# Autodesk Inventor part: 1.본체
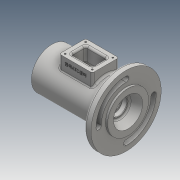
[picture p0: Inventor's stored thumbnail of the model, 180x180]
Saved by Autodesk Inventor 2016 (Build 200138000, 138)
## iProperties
Created: 2017-05
Part Number: 1.본체
Material: Generic
Document SubType Name: Modeling
Designer: Administrator
Density: 1 g/cm^3
Appearance: Default
Author: Administrator
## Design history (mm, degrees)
sketch "스케치1"
  geometry: L1 (-56, 31)-(59, 31); L2 (59, 31)-(59, 0); L3 (59, 0)-(-56, 0); L4 (-56, 0)-(-56, 31); L5 (56, 0)-(46, 0); L6 (46, 0)-(46, 53); L7 (46, 53)-(56, 53); L8 (56, 53)-(56, 0); 1 further point
  constraints: 16 end point, 4 parallel, 2 horizontal, 2 perpendicular, 2 point on line
  dimensions: "d0" = 115 distance of L1.start L1.end; "d1" = 62 diameter of L1 L3; "d2" = 13 distance between parallel lines of L2 L6; "d3" = 3 distance between parallel lines of L2 L8; "d4" = 106 diameter of L7 L3; "d5" = 56 distance from line of point (0, 0) L4
revolve "회전1" sketch "스케치1" stored, may be unused: angle "d6" = 90 deg
node "작업 평면1"
sketch "스케치2"
  geometry: L1 (-25, -20)-(25, -20); L2 (25, -20)-(25, 20); L3 (25, 20)-(-25, 20); L4 (-25, 20)-(-25, -20); L5 (-25, -20)-(25, 20); L6 (25, -20)-(-25, 20); 1 further point
  constraints: 12 end point, 2 midpoint, 2 parallel, 1 horizontal, 1 perpendicular
  dimensions: "d8" = 50 distance of L2.end L3.end; "d9" = 40 distance of L3.end L1.start
extrude "돌출1" join sketch "스케치2" stored distance "d10" = 10; taper "d11" = 0 deg
sketch "스케치3"
  geometry: L1 (-56, -31)-(-59, -31) reference; L2 (-59, -31)-(-59, 31) reference; L3 (-59, 31)-(-56, 31) reference; L4 (-56, 31)-(-56, 53) reference; L5 (-56, 53)-(-46, 53) reference; L6 (-46, 53)-(-46, 31) reference; L7 (-46, 31)-(-25, 31) reference; L8 (-25, 31)-(-25, 44) reference; L9 (-25, 44)-(25, 44) reference; L10 (25, 44)-(25, 31) reference; L11 (25, 31)-(56, 31) reference; L12 (56, 31)-(56, -31) reference; L13 (56, -31)-(-46, -31) reference; L14 (-46, -31)-(-46, -53) reference; L15 (-46, -53)-(-56, -53) reference; L16 (-56, -53)-(-56, -31) reference; L17 (56, 0)-(-59, 0); L18 (56, 0)-(47, 0); L19 (47, 0)-(47, 21); L20 (47, 21)-(56, 21); L21 (56, 21)-(56, 0); L22 (47, 0)-(44, 0); L23 (44, 0)-(44, 24); L24 (44, 24)-(47, 24); L25 (47, 24)-(47, 0); L26 (44, 0)-(35, 0); L27 (35, 0)-(35, 20); L28 (35, 20)-(44, 20); L29 (44, 20)-(44, 0); L30 (35, 0)-(31.75, 0); L31 (31.75, 0)-(31.75, 17.5); L32 (31.75, 17.5)-(35, 17.5); L33 (35, 17.5)-(35, 0); L34 (31.75, 0)-(30, 0); L35 (30, 0)-(30, 18.5); L36 (30, 18.5)-(31.75, 18.5); L37 (31.75, 18.5)-(31.75, 0); L38 (30, 0)-(19, 0); L39 (19, 0)-(19, 17.5); L40 (19, 17.5)-(30, 17.5); L41 (30, 17.5)-(30, 0); L42 (19, 0)-(-19, 0); L43 (-19, 0)-(-19, 23); L44 (-16, 26)-(16, 26); L45 (19, 23)-(19, 0); L46 (-19, 0)-(-30, 0); L47 (-30, 0)-(-30, 17.2); L48 (-29.7, 17.5)-(-19, 17.5); L49 (-19, 17.5)-(-19, 0); L50 (-30, 0)-(-35, 0); L51 (-35, 0)-(-35, 13.5); L52 (-32, 16.5)-(-30, 16.5); L53 (-30, 16.5)-(-30, 0); L54 (-35, 0)-(-37.7, 0); L55 (-37.7, 0)-(-37.7, 10); L56 (-37.7, 10)-(-35, 10); L57 (-35, 10)-(-35, 0); L58 (-37.7, 0)-(-45, 0); L59 (-45, 0)-(-45, 12.5); L60 (-45, 12.5)-(-38, 12.5); L61 (-37.7, 12.2)-(-37.7, 0); L62 (-45, 0)-(-59, 0); L63 (-59, 0)-(-59, 22); L64 (-59, 22)-(-46.818, 16.779)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; A1 r 3 centre (16, 23) between (19, 23) and (16, 26); A2 r 3 centre (-16, 23) between (-16, 26) and (-19, 23); A3 r 3 centre (-32, 13.5) between (-32, 16.5) and (-35, 13.5); A4 r 3 centre (-48, 14.022) between (-45, 14.022) and (-46.818, 16.779); A5 r 0.3 centre (-29.7, 17.2) between (-29.7, 17.5) and (-30, 17.2); A6 r 0.3 centre (-38, 12.2) between (-37.7, 12.2) and (-38, 12.5); 5 further points
  constraints: 98 end point, 23 parallel, 12 horizontal, 12 perpendicular, 12 point on circle, 12 tangent, 9 point on line, 6 centre point, 3 equal radius, 2 collinear, 2 midpoint
  dimensions: "d12" = 12 distance between parallel lines of L23 L12; "d13" = 3 distance between parallel lines of L29 L19; "d14" = 21 distance between parallel lines of L27 L12; "d15" = 26 distance between parallel lines of L35 L21; "d16" = 1.75 distance of L35.end L36.end; "d17" = 38 distance of point (-19, 26) point (19, 26); "d18" = 60 distance between parallel lines of L47 L35; "d19" = 5 distance between parallel lines of L47 L51; "d20" = 14 distance between parallel lines of L65 L2; "d21" = 11 distance of point (-30, 17.5) L48.end; "d22" = 2.7 distance between parallel lines of L51 L55; "d23" = 42 diameter of L20 L17; "d24" = 48 diameter of L24 L22; "d25" = 40 diameter of L28 L17; "d26" = 35 diameter of L32 L30; "d27" = 37 diameter of L36 L17; "d28" = 52 diameter of L44 L42; "d29" = 35 diameter of L48 L46; "d30" = 33 diameter of L52 L17; "d31" = 20 diameter of L56 L17; "d32" = 25 diameter of L60 L17; "d33" = 32 diameter of point (-45, 16) L17; "d34" = 44 diameter of L63.end L17; "d35" = 3 radius of A1; "d36" = 0.3 radius of A5; "d37" = 0.3 radius of A6
revolve "회전2" sketch "스케치3" stored, may be unused: angle "d38" = 90 deg
node "작업 평면4"
  node "작업 평면3"
sketch "스케치5"
  geometry: L1 (-56, -31)-(-56, 31) reference; L2 (-25, 44)-(25, 44) reference; 2 further points
  constraints: 1 other
  dimensions: "d42" = 56 distance from line of point (0, 36) L1; "d43" = 8 distance from line of point (0, 36) L2
feature "엠보싱1" sketch "스케치5" dims "d0" = 115, "d1" = 62, "d2" = 13, "d3" = 3, "d4" = 106, "d5" = 56, "d44" = 0.5, "d45" = 0
sketch "스케치6"
  geometry: L1 (-16, -11)-(16, -11); L2 (16, -11)-(16, 11); L3 (16, 11)-(-16, 11); L4 (-16, 11)-(-16, -11); L5 (-16, -11)-(16, 11); L6 (16, -11)-(-16, 11); 1 further point
  constraints: 12 end point, 2 midpoint, 2 parallel, 1 horizontal, 1 perpendicular
  dimensions: "d46" = 32 distance of L2.end L3.end; "d47" = 22 distance of L1.end L2.end
extrude "돌출2" cut sketch "스케치6" stored distance "d48" = 10; taper "d49" = 0 deg
fillet "모깎기1" dims "d50" = 3
fillet "모깎기2" dims "d51" = 3
fillet "모깎기3" dims "d52" = 3
sketch "스케치7"
  geometry: L1 (-20.5, -15.5)-(20.5, -15.5); L2 (20.5, -15.5)-(20.5, 15.5); L3 (20.5, 15.5)-(-20.5, 15.5); L4 (-20.5, 15.5)-(-20.5, -15.5); L5 (-20.5, -15.5)-(20.5, 15.5); L6 (20.5, -15.5)-(-20.5, 15.5); 5 further points
  constraints: 12 end point, 4 coincident, 2 midpoint, 2 parallel, 1 horizontal, 1 perpendicular
  dimensions: "d53" = 31 distance of L3.end L1.start; "d54" = 41 distance of L2.end L3.end
hole "구멍1" sketch "스케치7" at (-20.5, 15.5), (20.5, 15.5), (20.5, -15.5), (-20.5, -15.5) diameter "d55" = 2.459; stored, may be unused: countersink angle "d59" = 90 deg, drill point angle "d61" = 118 deg; dims "d56" = 6, "d57" = 4, "d58" = 2, "d60" = 8
sketch "스케치8"
  geometry: L1 (0, -53)-(0, 53); L2 (-53, 0)-(53, 0); A1 r 53 centre (0, 0) between (0, -53) and (0, 53) reference; A2 r 41.5 centre (0, 0) between (0, -41.5) and (-41.5, 0); A3 r 4 centre (0, -41.5) between (0, -45.5) and (0, -37.5); A4 r 4 centre (-41.5, 0) between (-37.5, 0) and (-45.5, 0); A5 r 4 centre (0, 41.5) between (0, 45.5) and (0, 37.5); A6 r 4 centre (41.5, 0) between (37.5, 0) and (45.5, 0); A7 r 37.5 centre (0, 0) between (-37.5, 0) and (0, -37.5); A8 r 37.5 centre (0, 0) between (37.5, 0) and (0, 37.5); A9 r 45.5 centre (0, 0) between (-45.5, 0) and (0, -45.5); A10 r 45.5 centre (0, 0) between (45.5, 0) and (0, 45.5); 2 further points
  constraints: 24 point on circle, 9 centre point, 5 tangent, 4 end point, 4 point on line, 3 coincident, 2 midpoint, 1 horizontal, 1 horizontal alignment, 1 vertical, 1 vertical alignment
  dimensions: "d62" = 83 diameter of A2; "d63" = 8 diameter of A3; "d64" = 8 diameter of A4; "d65" = 45.5 radius of A9; "d66" = 45.5 radius of A10; "d67" = 37.5 radius of A8
extrude "돌출3" cut sketch "스케치8" distance "d68" = 10; taper "d69" = 0 deg
fillet "모깎기4" dims "d70" = 3
chamfer "모따기1" distance "d71" = 0.7; stored, may be unused: second distance "d72" = 2, angle "d73" = 30 deg
chamfer "모따기2" distance "d74" = 1; stored, may be unused: second distance "d75" = 2, angle "d76" = 30 deg
feature "스레드1" dims "d77" = 10, "d78" = 0
chamfer "모따기3" distance "d79" = 1; stored, may be unused: second distance "d80" = 2, angle "d81" = 30 deg
node "솔리드1"
node "절단 모서리 투영1"
other parameters: "d7" = 44, "d40" = 90 deg
